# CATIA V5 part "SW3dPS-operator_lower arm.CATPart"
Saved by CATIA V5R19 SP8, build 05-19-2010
Part number: SW3dPS-operator_lower arm
Revision: ANY
Definition: SW3dPS-operator_lower arm
Source: Unknown
Bounding box of the stored display mesh (mm): x -48.26 to 48.26, y -307.34 to 48.26, z -48.26 to 48.26
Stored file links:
  G:\EU_thinkMotion\CFAO_2010\MMS_groupe1\MMS_groupe1\OK\rragonneau\rragonneau\SW3dPS-operator_lower arm.CATPart
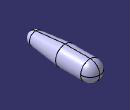
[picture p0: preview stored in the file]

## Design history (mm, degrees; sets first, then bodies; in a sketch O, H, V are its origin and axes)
Body1 "NONE" (main body)
  Solid1 "Manifold Solid #12118": solid without history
